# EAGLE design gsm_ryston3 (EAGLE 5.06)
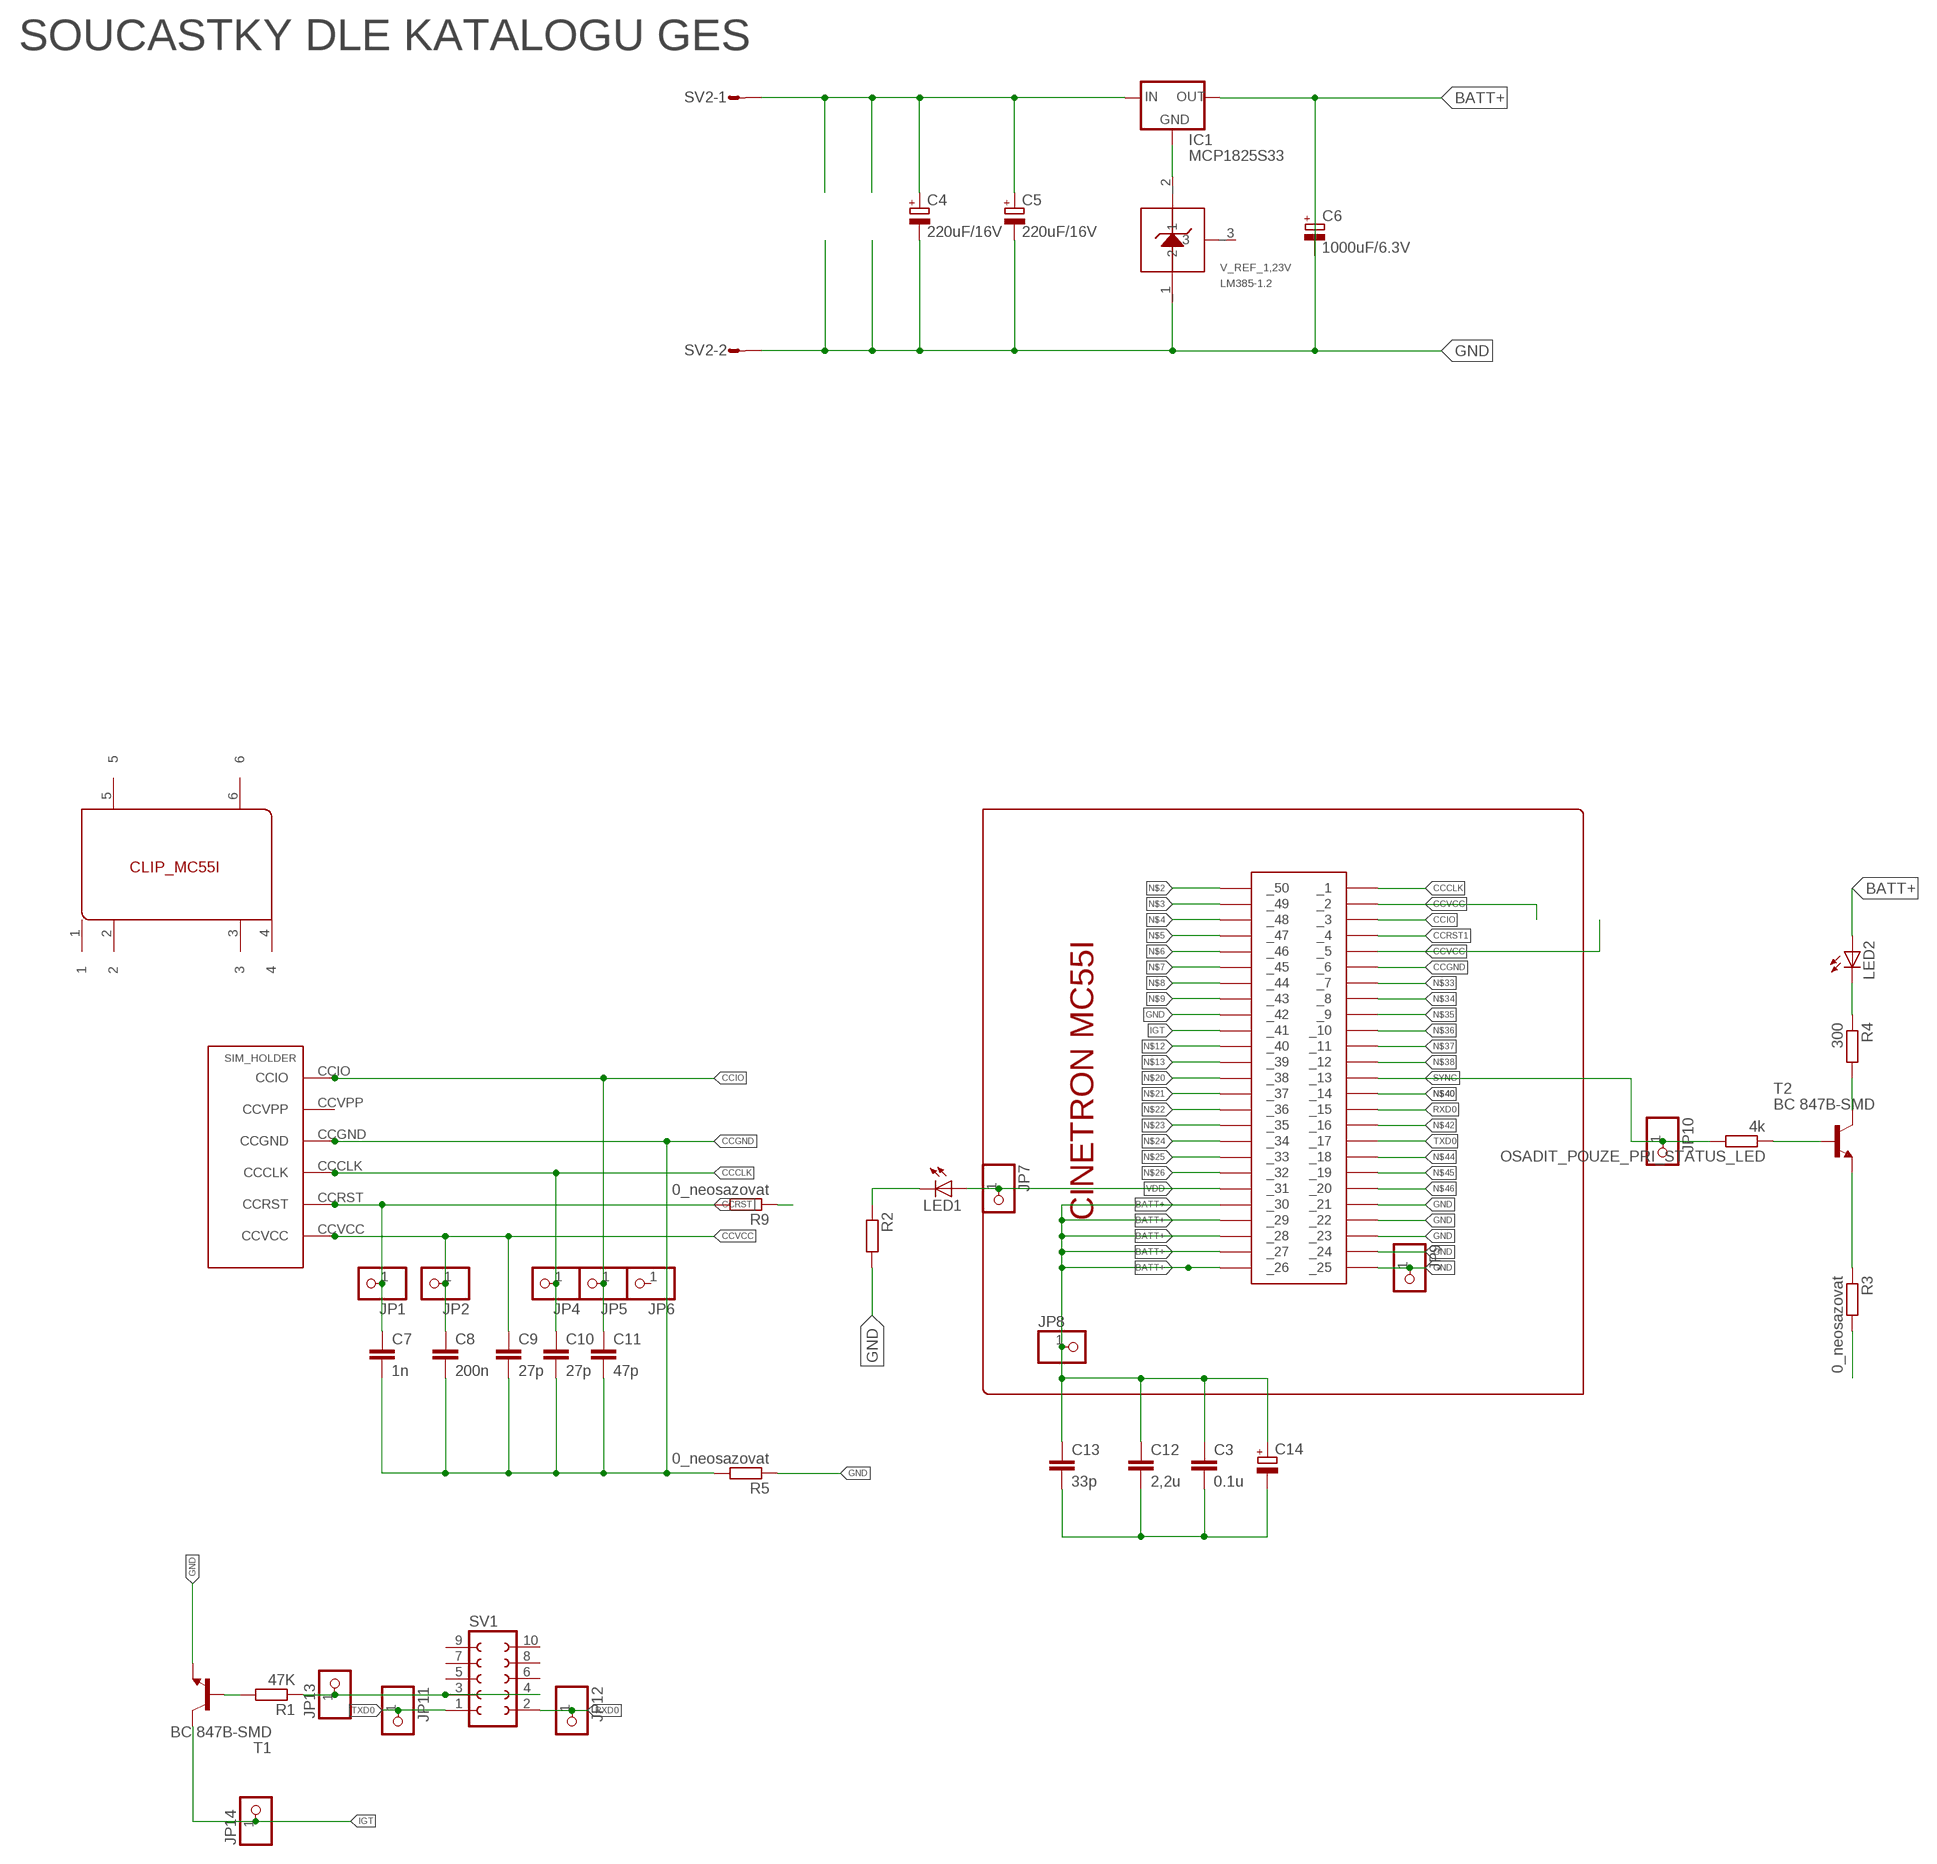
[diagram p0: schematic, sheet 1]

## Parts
C3  0.1u  C-EUC1206K  [C1206K]
C4  220uF/16V  CPOL-EUE2.5-6  [E2,5-6]
C5  220uF/16V  CPOL-EUE2.5-6  [E2,5-6]
C6  1000uF/6.3V  CPOL-EUF  [PANASONIC_F]
C7  1n  C-EUC1206K  [C1206K]
C8  200n  C-EUC1206K  [C1206K]
C9  27p  C-EUC1206K  [C1206K]
C10  27p  C-EUC1206K  [C1206K]
C11  47p  C-EUC1206K  [C1206K]
C12  2,2u  C-EUC1206K  [C1206K]
C13  33p  C-EUC1206K  [C1206K]
C14  CPOL-EUE2.5-6  [E2,5-6]
GND  CLIP_MC55I  [CLIP]
IC1  MCP1825S33  78XXL  [78XXL]
JP1  PINHD-1X1  [1X01]
JP2  PINHD-1X1  [1X01]
JP4  PINHD-1X1  [1X01]
JP5  PINHD-1X1  [1X01]
JP6  PINHD-1X1  [1X01]
JP7  PINHD-1X1  [1X01]
JP8  PINHD-1X1  [1X01]
JP9  PINHD-1X1  [1X01]
JP10  PINHD-1X1  [1X01]
JP11  PINHD-1X1  [1X01]
JP12  PINHD-1X1  [1X01]
JP13  PINHD-1X1  [1X01]
JP14  PINHD-1X1  [1X01]
LED1  LEDCHIPLED_1206  [CHIPLED_1206]
LED2  LEDCHIPLED_1206  [CHIPLED_1206]
OSADIT_POUZE_PRI_STATUS_LED  4k  R-EU_M1206  [M1206]
R1  47K  R-EU_M1206  [M1206]
R2  R-EU_M1206  [M1206]
R3  0_neosazovat  R-EU_M1206  [M1206]
R4  300  R-EU_M1206  [M1206]
R5  0_neosazovat  R-EU_M1206  [M1206]
R9  0_neosazovat  R-EU_M1206  [M1206]
SIM_HOLDER  SIM_CINETRON_MC55I  [SIM_HOLDER]
SV1  FE05-2W  [FE05-2W]
SV2  L02P  [L02P]
T1  BC 847B-SMD  BC847  [SOT23]
T2  BC 847B-SMD  BC847  [SOT23]
U$2  CON  [CON]
V_REF_1,23V  LM385-1.2  [TO-92]

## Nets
5VDD: C4.+ C5.+ IC1.IN SV2.1
BATT+: C3.1 C6.+ C12.1 C13.1 C14.+ IC1.OUT JP8.1 LED2.A U$2.26(_26) U$2.27(_27) U$2.28(_28) U$2.29(_29) U$2.30(_30)
CCCLK: C10.1 JP4.1 SIM_HOLDER.CCCLK U$2.1(_1)
CCGND: C7.2 C8.2 C9.2 C10.2 C11.2 R5.2 SIM_HOLDER.CCGND U$2.6(_6)
CCIO: C11.1 JP5.1 SIM_HOLDER.CCIO U$2.3(_3)
CCRST: C7.1 JP1.1 R9.2 SIM_HOLDER.CCRST
CCRST1: R9.1 U$2.4(_4)
CCVCC: C8.1 C9.1 JP2.1 SIM_HOLDER.CCVCC U$2.2(_2) U$2.5(_5)
GND: C3.2 C4.- C5.- C6.- C12.2 C13.2 C14.- JP9.1 R2.2 R3.2 R5.1 SV2.2 T1.2(E) U$2.21(_21) U$2.22(_22) U$2.23(_23) U$2.24(_24) U$2.42(_42) U$2._25 V_REF_1,23V._1
IGT: JP14.1 T1.3(C) U$2.41(_41)
N$1: IC1.GND V_REF_1,23V._2
N$2: U$2.50(_50)
N$3: U$2.49(_49)
N$4: U$2.48(_48)
N$5: U$2.47(_47)
N$6: U$2.46(_46)
N$7: U$2.45(_45)
N$8: U$2.44(_44)
N$9: U$2.43(_43)
N$10: LED1.C R2.1
N$11: OSADIT_POUZE_PRI_STATUS_LED.1 T2.1(B)
N$12: U$2.40(_40)
N$13: U$2.39(_39)
N$14: R1.2 T1.1(B)
N$15: JP13.1 R1.1 SV1.3 SV1.4
N$16: R4.2 T2.3(C)
N$17: LED2.C R4.1
N$18: R3.1 T2.2(E)
N$20: U$2.38(_38)
N$21: U$2.37(_37)
N$22: U$2.36(_36)
N$23: U$2.35(_35)
N$24: U$2.34(_34)
N$25: U$2.33(_33)
N$26: U$2.32(_32)
N$33: U$2.7(_7)
N$34: U$2.8(_8)
N$35: U$2.9(_9)
N$36: U$2.10(_10)
N$37: U$2.11(_11)
N$38: U$2.12(_12)
N$40: U$2.14(_14)
N$42: U$2.16(_16)
N$44: U$2.18(_18)
N$45: U$2.19(_19)
N$46: U$2.20(_20)
RXD0: JP12.1 SV1.2 U$2.15(_15)
SYNC: JP10.1 OSADIT_POUZE_PRI_STATUS_LED.2 U$2.13(_13)
TXD0: JP11.1 SV1.1 U$2.17(_17)
VDD: JP7.1 LED1.A U$2.31(_31)
Unconnected: GND.1 GND.2 GND.3 GND.4 GND.5 GND.6 JP6.1 SV1.5 SV1.6 SV1.7 SV1.8 SV1.9 SV1.10 V_REF_1,23V._3

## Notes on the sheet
- SOUCASTKY DLE KATALOGU GES

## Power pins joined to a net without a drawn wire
CCVPP: SIM_HOLDER.CCVPP

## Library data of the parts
C3 C7-C13 = rcl:C-EU: CAPACITOR, European symbol
C4-C6 C14 = rcl:CPOL-EU: POLARIZED CAPACITOR, European symbol
GND = clip_MC55I:CLIP_MC55I: clip pro MC55I
IC1 = v-reg:78XXL: VOLTAGE REGULATOR
JP1 JP2 JP4-JP14 = pinhead:PINHD-1X1: PIN HEADER
LED1 LED2 = led:LED: LED
OSADIT_POUZE_PRI_STATUS_LED R1-R5 R9 = rcl:R-EU_: RESISTOR, European symbol
SIM_HOLDER = sim_holder:SIM_CINETRON_MC55I: DRZAK SIM KARTY PRO MC55I
SV1 = con-lsta:FE05-2W: FEMALE HEADER
SV2 = con-amp-mt:L02P: AMP MT CONNECTOR
T1 T2 = transistor:BC847: NPN TRANSISTOR
U$2 = cinetron_MC55I :CON: Konektor pro GSM modul MC55i samicka (na BRD)
V_REF_1,23V = LM385-1.2:LM385-1.2: nampetova reference

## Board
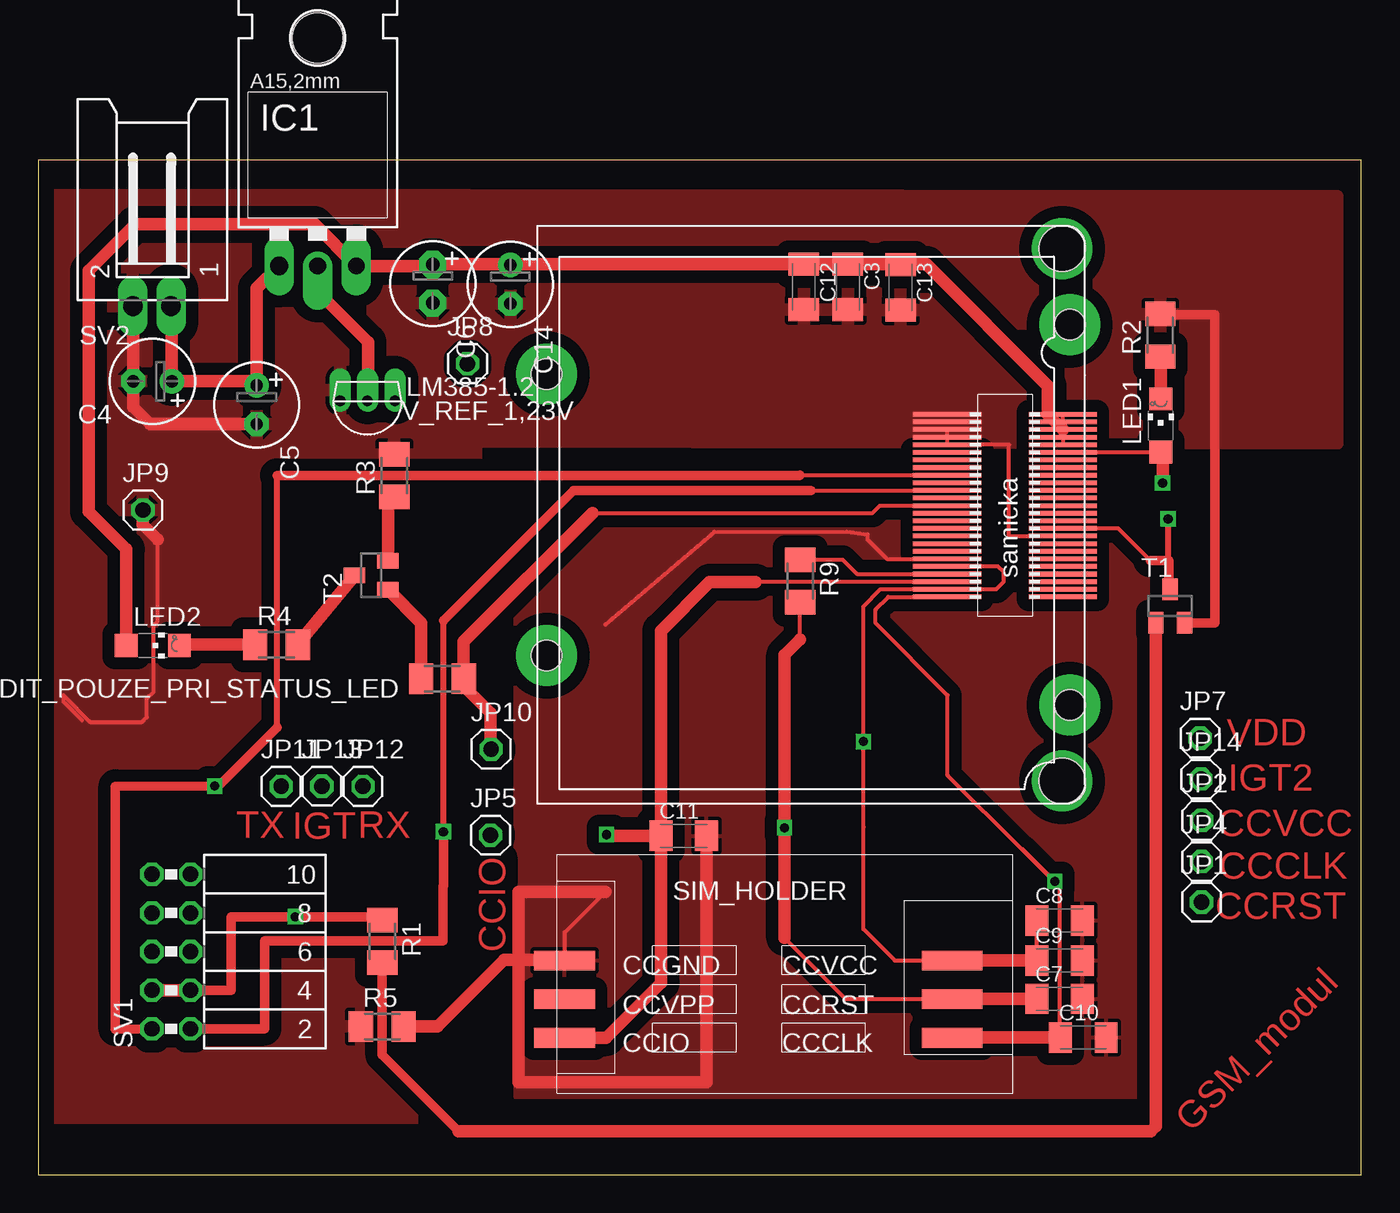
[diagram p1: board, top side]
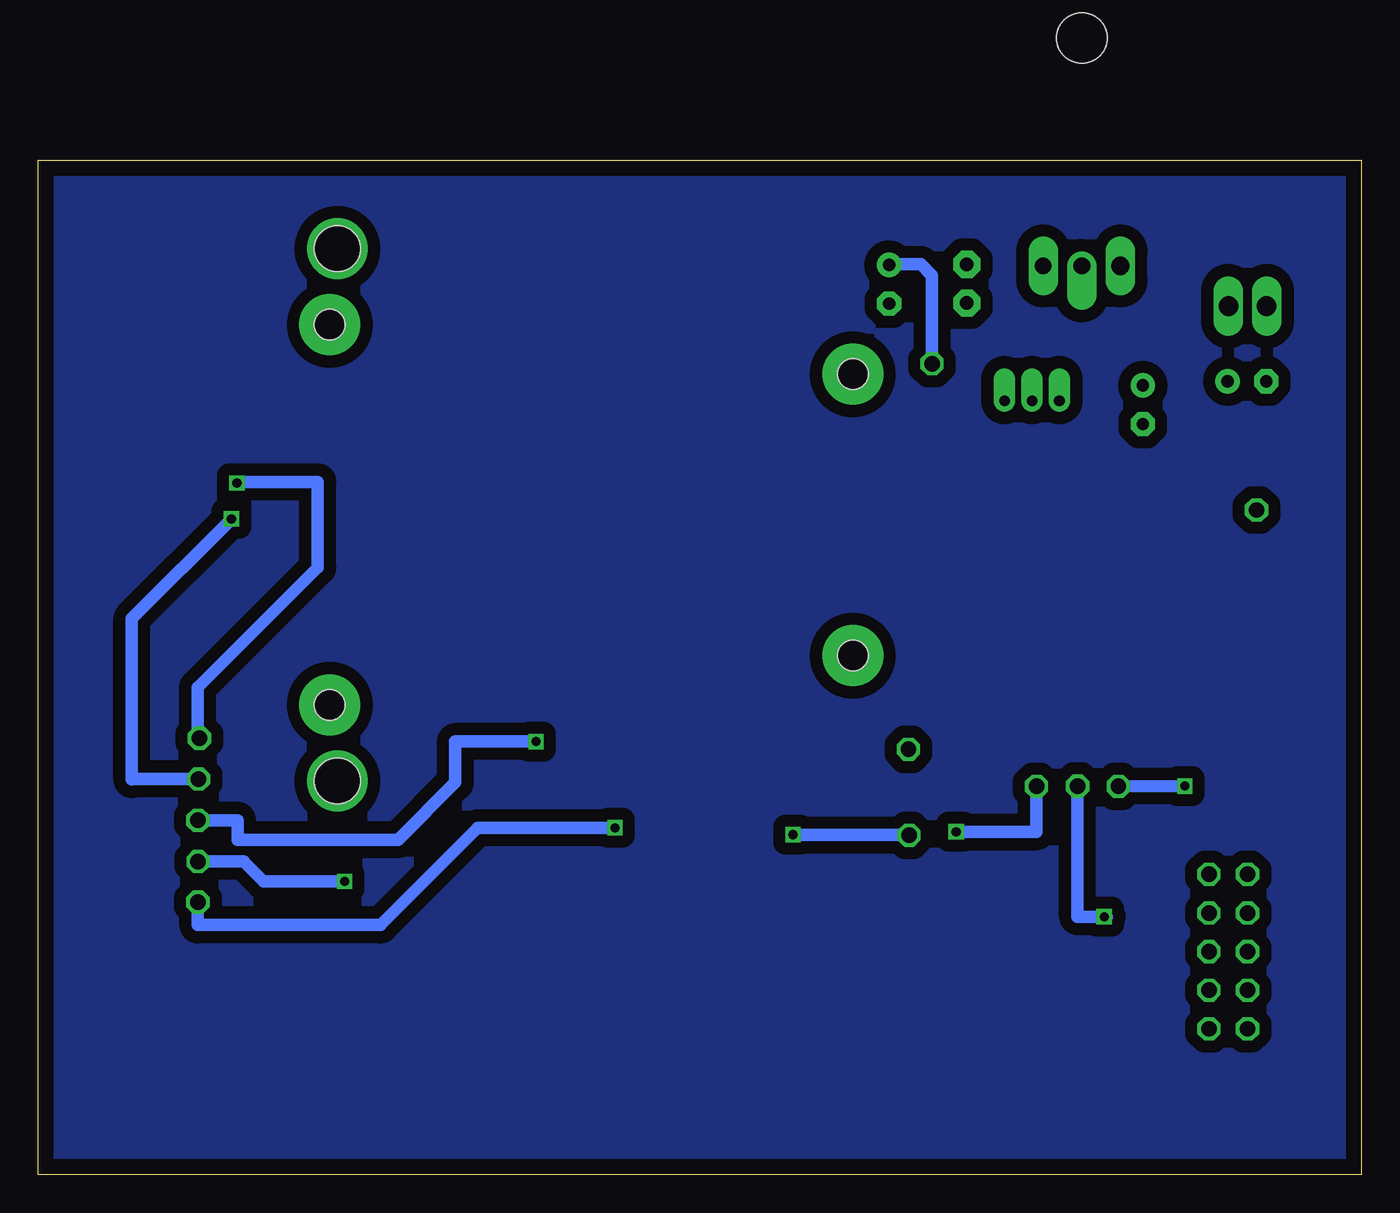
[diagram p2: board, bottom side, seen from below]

Size 87.02 x 66.71 mm. Coordinates in mm from the lower left corner, seen from the top.
Outline: 0,0 87.02,0 87.02,66.71 0,66.71 0,0
Copper layers (1*16): Top 0.035mm / dielectric 1.5mm / Bottom 0.035mm
Design rules "default *": minimum track width 10mil, minimum drill 24mil, track to track 5mil, track to pad 5mil, pad to pad 5mil, via to via 5mil, smd to smd 5mil, copper to edge 40mil, drill to drill 8mil, minimum pad ring 10mil, minimum via ring 8mil, stop-mask expansion 4mil, vias tented up to drill 0mil, thermal gap 10mil

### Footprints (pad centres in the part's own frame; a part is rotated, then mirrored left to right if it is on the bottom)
C1206K = smd 1.5 x 2: 1 -1.5,0; 2 1.5,0
E2,5-6 = drill 0.813 pad 1.6 round: + -1.27,0 | drill 0.813 pad 1.6 octagon: - 1.27,0
E2,5-6@1 = drill 0.9 pad 1.778 octagon: + -1.27,0; - 1.27,0
CLIP = drill 2 pad 4 round: 1 0,0; 2 5,-0.5; 3 30,-0.5; 4 35,0; 5 8.25,33.9; 6 26.75,33.9 | hole 2: 8.25,33.9; 26.75,33.9; 5,-0.5; 30,-0.5 | hole 3: 0,0; 35,0
78XXL = drill 1.1 pad 1.93 offset: GND 0,-3.81 | drill 1.2 pad 1.93 long: IN -2.54,-3.81 | drill 1.1 pad 1.93 long: OUT 2.54,-3.81 | hole 3.302: 0,11.176
1X01 = drill 1.016 octagon: 1 0,0
CHIPLED_1206 = smd 1.5 x 1.5: A 0,-1.75; C 0,1.75
M1206 = smd 1.6 x 2: 1 -1.4,0; 2 1.4,0
SIM_HOLDER = smd 4 x 1.3: CCCLK 26,3.65; CCGND 0.5,8.73; CCIO 0.5,3.65; CCRST 26,6.19; CCVCC 26,8.73; CCVPP 0.5,6.19
FE05-2W = drill 1.016 octagon: 1 -5.08,1.27; 2 -5.08,-1.27; 3 -2.54,1.27; 4 -2.54,-1.27; 5 0,1.27; 6 0,-1.27; 7 2.54,1.27; 8 2.54,-1.27; 9 5.08,1.27; 10 5.08,-1.27
L02P = drill 1.3 long: 1 1.25,-6.25; 2 -1.25,-6.25
SOT23 = smd 1 x 1.4: 1 -0.95,-1.1; 2 0.95,-1.1; 3 0,1.1
CON = smd 4.5 x 0.3: 1 3.8,6.05; 2 3.8,5.55; 3 3.8,5.05; 4 3.8,4.55; 5 3.8,4.05; 6 3.8,3.55; 7 3.8,3.05; 8 3.8,2.55; 9 3.8,2.05; 10 3.8,1.55; 11 3.8,1.05; 12 3.8,0.55; 13 3.8,0.05; 14 3.8,-0.45; 15 3.8,-0.95; 16 3.8,-1.45; 17 3.8,-1.95; 18 3.8,-2.45; 19 3.8,-2.95; 20 3.8,-3.45; 21 3.8,-3.95; 22 3.8,-4.45; 23 3.8,-4.95; 24 3.8,-5.45; 26 -3.8,-5.95; 27 -3.8,-5.45; 28 -3.8,-4.95; 29 -3.8,-4.45; 30 -3.8,-3.95; 31 -3.8,-3.45; 32 -3.8,-2.95; 33 -3.8,-2.45; 34 -3.8,-1.95; 35 -3.8,-1.45; 36 -3.8,-0.95; 37 -3.8,-0.45; 38 -3.8,0.05; 39 -3.8,0.55; 40 -3.8,1.05; 41 -3.8,1.55; 42 -3.8,2.05; 43 -3.8,2.55; 44 -3.8,3.55; 45 -3.8,3.05; 46 -3.8,4.05; 47 -3.8,4.55; 48 -3.8,5.05; 49 -3.8,5.55; 50 -3.8,6.05; _25 3.8,-5.95
TO-92 = drill 0.7 pad 1.422 offset: _1 -1.8,0; _2 0,0; _3 1.8,0

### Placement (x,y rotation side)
C3  53.25,58.37 270 top
C4  7.53,52.17 180 top
C5  14.37,50.62 270 top
C6  1000uF/6.3V  [E2,5-6@1]  25.95,58.59 270 top
C7  67.18,11.56 0 top
C8  67.18,16.71 0 top
C9  67.18,14.08 0 top
C10  68.73,9.02 0 top
C11  42.46,22.28 0 top
C12  50.35,58.37 270 top
C13  56.72,58.34 270 top
C14  31.06,58.55 270 top
GND  67.34,25.88 90 top
IC1  18.39,63.56 0 top
JP1  76.52,17.92 0 top
JP2  76.52,23.29 0 top
JP4  76.5,20.59 0 top
JP5  29.75,22.31 0 top
JP6  not placed on the board
JP7  76.41,28.7 0 top
JP8  28.24,53.33 0 top
JP9  6.89,43.7 0 top
JP10  29.79,27.97 0 top
JP11  15.99,25.53 0 top
JP12  21.37,25.53 0 top
JP13  18.67,25.54 0 top
JP14  76.46,26.01 0 top
LED1  73.82,49.26 0 top
LED2  7.55,34.8 270 top
OSADIT_POUZE_PRI_STATUS_LED  26.59,32.6 0 top
R1  22.64,15.34 270 top
R2  73.8,55.19 90 top
R3  23.43,45.96 90 top
R4  15.68,34.85 0 top
R5  22.64,9.74 0 top
R9  50.11,39.03 270 top
SIM_HOLDER  34.11,5.35 0 top
SV1  8.76,14.67 90 top
SV2  7.49,63.36 0 top
T1  74.45,37.39 0 top
T2  21.91,39.41 90 top
U$2  63.59,44.04 180 top
V_REF_1,23V  21.67,50.88 0 top

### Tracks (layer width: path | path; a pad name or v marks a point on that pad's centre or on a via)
5VDD
  Top 0.813: 15.67,59.35 IC1.IN 14.37,58.28 C5.+ 14.1,52.17 C4.+ 8.8,57.05 SV2.1
BATT+
  Top 0.254: U$2.28 U$2.29 | U$2.29 U$2.30 | U$2.28 U$2.29 | U$2.28 U$2.27 U$2.26
  Top 0.813: U$2.28 66.42,49.96 66.42,51.85 58.42,59.86 56.68,59.86 | 30.88,59.86 28.26,59.86 C6.+ 25.85,59.75 IC1.OUT 18.19,62.5 6.39,62.5 3.32,59.44 3.32,43.61 5.8,41.13 LED2.A | 30.88,59.86 50.54,59.86 | 50.54,59.86 53.19,59.86 | 53.19,59.86 56.68,59.86 | C14.+ 30.92,59.82 30.88,59.86 | C12.1 50.53,59.87 50.54,59.86 | C3.1 53.2,59.87 53.19,59.86 | C13.1 56.69,59.84 56.68,59.86
  Bottom 0.813: JP8.1 28.24,59.12 28.98,59.86 31.02,59.86 C14.+
CCCLK  (via drill 0.6)
  Top 0.254: 60.13,9.02 67.19,9.02 67.19,18.87 64.68,21.39 | 64.68,21.39 59.8,26.26 59.8,31.52 55.06,36.26 55.06,37.15 55.9,37.99 59.78,37.99 U$2.1 | 64.68,21.39 64.75,21.39 v66.86,19.28
  Top 0.813: C10.1 60.13,9.02 SIM_HOLDER.CCCLK
  Bottom 0.813: v66.86,19.28 72.18,19.28 73.49,20.59 JP4.1
CCGND
  Top 0.254: 37.31,18.61 34.64,15.94 34.64,14.11 SIM_HOLDER.CCGND | U$2.6 55.81,40.49 54.54,41.76 54.54,42.1 53.19,42.28 44.47,42.27 37.31,36.17
  Top 0.813: R5.2 26.29,9.74 30.66,14.11 34.58,14.11 SIM_HOLDER.CCGND | 37.31,18.61 31.61,18.61 31.61,6.08 43.96,6.08 C11.2
  pour Top (isolate 0.813): 31.4,5.07 31.4,46.25 85.46,46.25 85.46,5.07
CCIO  (via drill 0.6)
  Top 0.254: U$2.3 47.18,38.99 47.18,38.96
  Top 0.813: SIM_HOLDER.CCIO 37.35,9 40.97,12.61 C11.1 | C11.1 40.96,35.76 44.17,38.96 47.18,38.96 | C11.1 37.39,22.28 v37.39,22.35
  Bottom 0.813: v37.39,22.35 29.75,22.35 JP5.1
CCRST  (via drill 0.6)
  Top 0.254: 60.13,11.56 53.1,11.56 49.08,15.57 | 50.11,35.19 R9.2
  Top 0.813: C7.1 60.13,11.56 SIM_HOLDER.CCRST | 49.08,15.57 v49.08,22.81 49.08,34.16 50.11,35.19
  Bottom 0.813: v49.08,22.81 58.11,22.81 64.5,16.42 76.52,16.42 JP1.1
CCRST1
  Top 0.254: U$2.4 53.85,39.49 52.91,40.44 50.12,40.44 R9.1
CCVCC  (via drill 0.6)
  Top 0.254: U$2.2 | C9.1 C8.1 | SIM_HOLDER.CCVCC 56.33,14.08 54.26,16.15 54.26,22.86 | 54.26,22.86 54.26,37.35 55.41,38.49 U$2.2 | U$2.2 | U$2.5 63.12,39.99 63.5,39.61 63.5,38.99 63,38.49 U$2.2 | U$2.2 | 54.26,22.86 54.28,22.86 v54.28,28.47
  Top 0.813: C9.1 SIM_HOLDER.CCVCC
  Bottom 0.813: v54.28,28.47 59.6,28.47 59.6,25.78 63.36,22.02 73.91,22.02 73.91,23.29 JP2.1
GND
  Top 0.254: U$2.23 U$2.22 U$2.21 63.84,47.99 63.84,41.99 67.39,41.99 U$2.42 | 7.86,41.77 7.86,36.39 7.6,36.13 7.6,31.75 7.16,31.31 7.16,30.09 6.84,29.77 3.41,29.77 1.67,31.51 1.67,31.09 2.89,29.87
  Top 0.61: T1.2 77.37,36.29 77.37,56.57 73.8,56.57 R2.2
  Top 0.813: C5.- 7.39,49.36 6.27,50.47 6.27,52.16 C4.- 6.26,57.09 SV2.2 | JP9.1 6.89,42.74 7.86,41.77
  pour Top (isolate 0.813): 28.8,3.73 28.8,48.2 85.43,48.08 85.43,64.33 -0.09,64.44 -0.09,3.73
IGT  (via drill 0.6)
  Top 0.254: U$2.41 71.03,42.49 73.14,40.39
  Top 0.406: 74.37,40.31 74.31,40.37 v74.31,43.12
  Top 0.61: T1.3 74.37,38.49 74.37,40.31 74.37,40.39 73.14,40.39
  Bottom 0.813: v74.31,43.12 80.86,36.56 80.86,25.98 80.83,26.01 JP14.1
N$1
  Top 0.813: V_REF_1,23V._2 21.69,54.75 18.39,58.05 IC1.GND
N$10
  Top 0.813: LED1.C 73.82,53.77 R2.1
N$11
  Top 0.813: OSADIT_POUZE_PRI_STATUS_LED.1 25.19,36.27 T2.1
N$14
  Top 0.61: 27.66,2.86 22.64,7.87 R1.2
  Top 0.813: T1.1 73.5,3.16 73.19,2.86 27.66,2.86
N$15  (via drill 0.6)
  Top 0.61: SV1.4 10.63,12.13 12.68,12.13 12.68,16.95 v16.91,16.95 22.64,16.95 R1.1
  Top 0.813: SV1.3 10.63,12.13
  Bottom 0.813: 16.74,16.95 v16.91,16.95 18.67,16.95 JP13.1
N$16
  Top 0.813: T2.3 R4.2
N$17
  Top 0.813: R4.1 9.35,34.85 LED2.C
N$18
  Top 0.813: T2.2 23.01,44.14 R3.1
RXD0  (via drill 0.6)
  Top 0.254: U$2.15 50.7,44.99 50.7,45
  Top 0.406: 26.65,22.62 26.65,36.44
  Top 0.61: 26.65,36.44 35.21,45 50.7,45 50.82,45 | SV1.2 14.89,9.59 14.89,15.38 26.64,15.38 26.64,18.99 26.65,19 v26.65,22.54 26.65,22.62
  Bottom 0.813: v26.65,22.54 21.37,22.54 JP12.1
SYNC
  Top 0.254: 36.45,43.51 54.87,43.51 55.36,43.99 U$2.13
  Top 0.813: 36.45,43.51 27.99,35.06 OSADIT_POUZE_PRI_STATUS_LED.2 27.99,32.13 29.77,30.35 29.77,27.99 JP10.1
TXD0  (via drill 0.6)
  Top 0.254: 50.09,45.99 59.78,45.99 U$2.17
  Top 0.406: 15.72,29.39 15.72,45.97
  Top 0.61: 15.72,29.39 11.88,25.55 v11.62,25.55 5.09,25.53 5.09,9.56 SV1.1 | 50.09,45.99 50.07,45.97 15.72,45.97
  Bottom 0.813: v11.62,25.55 11.85,25.55 JP11.1
VDD  (via drill 0.6)
  Top 0.254: U$2.31 73.8,47.49 LED1.A
  Top 0.813: LED1.A 73.95,47.39 v73.95,45.48
  Bottom 0.813: v73.95,45.48 73.89,45.54 68.63,45.54 68.63,39.93 76.54,32.02 76.54,28.83 JP7.1
VSS
  pour Bottom (isolate 0.813): 0.47,-0.01 86.83,-0.01 86.83,66.03 0.47,66.03

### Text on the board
Top: VDD | IGT2 | TX | IGT | RX | CCVCC | CCIO | CCCLK | CCRST | GSM_modul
